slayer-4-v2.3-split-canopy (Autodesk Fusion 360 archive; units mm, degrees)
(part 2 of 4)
fillet "Fillet22" radius 6
extrude "Extrude11" new body sketch "center-lower" profile of L23 L25 C7 L29 L49 L50 L51 L52 L53 along normal blind 2 bodies "center-lower"
mirror "Mirror13" mirrorStitchTolerance 0.1
combine "Combine3"
fillet "Fillet28" radius 8
fillet "Fillet29" radius 5
fillet "Fillet30" radius 2
sketch "cam-mount-base" plane through (0, 0, 0) normal (0, 0, 1) x axis (1, 0, 0)
  line L1 (135, 0) -> (0, 0)
  line L2 (-104.9665, -10.02) -> (-84.9265, -10.02)
  line L3 (-104.9665, 10.02) -> (-104.9665, -10.02)
  line L4 (-84.9265, 10.02) -> (-104.9665, 10.02)
  line L5 (-84.9265, -10.02) -> (-84.9265, 10.02)
  line L6 (-165, 0) -> (0, 0)
  point P1 (0, 0)
  point P2 (0, 0)
  point P8 (0, 0)
  coincident P1 P2
  horizontal L1
  horizontal L2
  vertical L3
  horizontal L4
  vertical L5
  coincident P1 P8
  parallel L1 L6
  dimension "d275" distance L1 L2 = 10.02 (= "d276 / 2")
  dimension "d276" distance L2 L4 = 20.04
  dimension "d277" distance L3 L5 = 20.04 (= "d276")
extrude "Extrude15" new body sketch "cam-mount-base" profile of L2 L3 L4 L5 along normal blind 13 bodies "cam-mount-shell"
work_plane "WorkPlane1" sketch "cam-mount-base" AlongDistance 22.6
sketch "cam-mount-lens" plane through (0, 0, 22.6) normal (0, 0, 1) x axis (1, 0, 0)
  line L1 (-104.9665, 10.02) -> (-84.9265, 10.02)
  line L2 (-104.9665, -10.02) -> (-104.9665, 10.02)
  line L3 (-84.9265, -10.02) -> (-104.9665, -10.02)
  line L4 (-84.9265, 10.02) -> (-84.9265, -10.02)
  line L5 (-165, 0) -> (0, 0)
  line L6 (-94.9465, 10.02) -> (-94.9465, -10.02)
  circle C1 centre (-94.9465, 0) radius 7
  point P6 (-94.9465, 0)
  point P9 (-94.9465, -10.02)
  point P10 (-94.9465, 10.02)
  coincident P6 L5
  midpoint L3 P9
  midpoint L1 P10
  coincident P6 L6
  dimension "d281" diameter C1 = 14
loft "Loft1" sketch "cam-mount-lens"
shell "Shell1" outerThickness 1.5
extrude "Extrude16" add of existing geometry blind 2
move "Move1"
move "Move2"
sketch "Sketch25" plane through (0, 0, 2) normal (0, 0, 1) x axis (-1, 0, 0)
  line L1 (-29.0384, -18.7057) -> (-35.3306, -4.3323)
  line L2 (-7.8768, -19.0795) -> (-10.419, -18.9098)
  line L3 (10.419, -18.9098) -> (7.8768, -19.0795)
  line L4 (7.8768, 19.0795) -> (10.419, 18.9098)
  line L5 (-10.419, 18.9098) -> (-7.8768, 19.0795)
  line L6 (-35.3306, 4.3323) -> (-29.0384, 18.7057)
  line L7 (-35.4985, -3.5303) -> (-35.4985, 3.5303)
  line L8 (-28.2669, 6) -> (-24.7203, 6)
  line L9 (-29.2912, 10.6474) -> (-30.099, 8.8021)
  line L10 (-30.4985, -3) -> (-23.0892, -3)
  line L11 (-32.4985, 1) -> (-32.4985, -1)
  line L12 (-23.0892, 3) -> (-30.4985, 3)
  line L13 (15.3479, -5.782) -> (13.4133, -8.1699)
  line L14 (19.6919, -8.9044) -> (18.7852, -6.3678)
  line L15 (13.4936, -15.6979) -> (15.3167, -15.5763)
  line L16 (13.4133, 8.1699) -> (15.3479, 5.782)
  line L17 (15.3167, 15.5763) -> (13.4936, 15.6979)
  line L18 (18.7852, 6.3678) -> (19.6919, 8.9044)
  line L19 (-15.3479, 5.782) -> (-13.4133, 8.1699)
  line L20 (-19.6919, 8.9044) -> (-18.7852, 6.3678)
  line L21 (-13.4936, 15.6979) -> (-15.3167, 15.5763)
  line L22 (-13.4133, -8.1699) -> (-15.3479, -5.782)
  line L23 (-15.3167, -15.5763) -> (-13.4936, -15.6979)
  line L24 (-18.7852, -6.3678) -> (-19.6919, -8.9044)
  line L25 (-30.099, -8.8021) -> (-29.2912, -10.6474)
  line L26 (-24.7203, -6) -> (-28.2669, -6)
  line L27 (42, 0) -> (-35, 0)
  line L28 (42, -18.878) -> (42, 0)
  line L29 (-35, 0) -> (-35, -20)
  line L30 (0.0223, -24.9973) -> (-35, -20)
  line L31 (42, -18.878) -> (0.0223, -24.9973)
  line L32 (22.1379, -6.8345) -> (22.6368, -8.2301)
  line L33 (22.6368, 8.2301) -> (22.1379, 6.8345)
  arc A1 centre (-33.4985, -3.5303) radius 2 clockwise from (-35.3306, -4.3323) to (-35.4985, -3.5303)
  arc A2 centre (-24, -16.5) radius 5.5 clockwise from (-21.3581, -21.3239) to (-29.0384, -18.7057)
  arc A3 centre (-11.751, -38.8654) radius 20 clockwise from (-21.3581, -21.3239) to (-10.419, -18.9098)
  arc A4 centre (-9.0756, -37.0396) radius 18 clockwise from (-7.8768, -19.0795) to (-1.2965, -20.8073)
  arc A5 centre (0, -18.1019) radius 3 clockwise from (1.2965, -20.8073) to (-1.2965, -20.8073)
  arc A6 centre (9.0756, -37.0396) radius 18 clockwise from (1.2965, -20.8073) to (7.8768, -19.0795)
  arc A7 centre (11.751, -38.8654) radius 20 clockwise from (10.419, -18.9098) to (21.3581, -21.3239)
  arc A8 centre (24, -16.5) radius 5.5 clockwise from (25.7522, -11.2866) to (21.3581, -21.3239)
  arc A9 centre (24, 16.5) radius 5.5 clockwise from (21.3581, 21.3239) to (25.7522, 11.2866)
  arc A10 centre (11.751, 38.8654) radius 20 clockwise from (21.3581, 21.3239) to (10.419, 18.9098)
  arc A11 centre (9.0756, 37.0396) radius 18 clockwise from (7.8768, 19.0795) to (1.2965, 20.8073)
  arc A12 centre (0, 18.1019) radius 3 clockwise from (-1.2965, 20.8073) to (1.2965, 20.8073)
  arc A13 centre (-9.0756, 37.0396) radius 18 clockwise from (-1.2965, 20.8073) to (-7.8768, 19.0795)
  arc A14 centre (-11.751, 38.8654) radius 20 clockwise from (-10.419, 18.9098) to (-21.3581, 21.3239)
  arc A15 centre (-24, 16.5) radius 5.5 clockwise from (-29.0384, 18.7057) to (-21.3581, 21.3239)
  arc A16 centre (-33.4985, 3.5303) radius 2 clockwise from (-35.4985, 3.5303) to (-35.3306, 4.3323)
  arc A17 centre (-28.2669, 8) radius 2 clockwise from (-28.2669, 6) to (-30.099, 8.8021)
  arc A18 centre (-27.4591, 9.8453) radius 2 clockwise from (-29.2912, 10.6474) to (-26.5366, 11.6199)
  arc A19 centre (-30.4985, -1) radius 2 clockwise from (-30.4985, -3) to (-32.4985, -1)
  arc A20 centre (-30.4985, 1) radius 2 clockwise from (-32.4985, 1) to (-30.4985, 3)
  circle C1 centre (18.1019, 0) radius 1.05
  circle C2 centre (10, -10) radius 1.05
  circle C3 centre (24, -16.5) radius 1.55
  arc A21 centre (16.9019, -7.041) radius 2 clockwise from (15.3479, -5.782) to (18.7852, -6.3678)
  arc A22 centre (14.9837, -10.5874) radius 5 clockwise from (19.6919, -8.9044) to (15.3167, -15.5763)
  arc A23 centre (13.3604, -13.7024) radius 2 clockwise from (13.4936, -15.6979) to (12.0163, -12.2214)
  arc A24 centre (10, -10) radius 3 clockwise from (12.9804, -9.6573) to (12.0163, -12.2214)
  arc A25 centre (14.9673, -9.4289) radius 2 clockwise from (12.9804, -9.6573) to (13.4133, -8.1699)
  arc A26 centre (14.9673, 9.4289) radius 2 clockwise from (13.4133, 8.1699) to (12.9804, 9.6573)
  arc A27 centre (10, 10) radius 3 clockwise from (12.0163, 12.2214) to (12.9804, 9.6573)
  arc A28 centre (13.3604, 13.7024) radius 2 clockwise from (12.0163, 12.2214) to (13.4936, 15.6979)
  arc A29 centre (14.9837, 10.5874) radius 5 clockwise from (15.3167, 15.5763) to (19.6919, 8.9044)
  arc A30 centre (16.9019, 7.041) radius 2 clockwise from (18.7852, 6.3678) to (15.3479, 5.782)
  circle C4 centre (24, 16.5) radius 1.55
  circle C5 centre (10, 10) radius 1.05
  circle C6 centre (-10, 10) radius 1.05
  circle C7 centre (-24, 16.5) radius 1.55
  arc A31 centre (-16.9019, 7.041) radius 2 clockwise from (-15.3479, 5.782) to (-18.7852, 6.3678)
  arc A32 centre (-14.9837, 10.5874) radius 5 clockwise from (-19.6919, 8.9044) to (-15.3167, 15.5763)
  arc A33 centre (-13.3604, 13.7024) radius 2 clockwise from (-13.4936, 15.6979) to (-12.0163, 12.2214)
  arc A34 centre (-10, 10) radius 3 clockwise from (-12.9804, 9.6573) to (-12.0163, 12.2214)
  arc A35 centre (-14.9673, 9.4289) radius 2 clockwise from (-12.9804, 9.6573) to (-13.4133, 8.1699)
  arc A36 centre (-14.9673, -9.4289) radius 2 clockwise from (-13.4133, -8.1699) to (-12.9804, -9.6573)
  arc A37 centre (-10, -10) radius 3 clockwise from (-12.0163, -12.2214) to (-12.9804, -9.6573)
  arc A38 centre (-13.3604, -13.7024) radius 2 clockwise from (-12.0163, -12.2214) to (-13.4936, -15.6979)
  arc A39 centre (-14.9837, -10.5874) radius 5 clockwise from (-15.3167, -15.5763) to (-19.6919, -8.9044)
  arc A40 centre (-16.9019, -7.041) radius 2 clockwise from (-18.7852, -6.3678) to (-15.3479, -5.782)
  circle C8 centre (-24, -16.5) radius 1.55
  circle C9 centre (-10, -10) radius 1.05
  circle C10 centre (-18.1019, 0) radius 1.05
  circle C11 centre (0, -18.1019) radius 1.05
  circle C12 centre (0, 18.1019) radius 1.05
  arc A41 centre (0, 3.3668) radius 9 clockwise from (-7.5, 8.3417) to (7.5, 8.3417)
  arc A42 centre (10, 10) radius 3 clockwise from (8.3417, 7.5) to (7.5, 8.3417)
  arc A43 centre (3.3668, 0) radius 9 clockwise from (8.3417, 7.5) to (8.3417, -7.5)
  arc A44 centre (10, -10) radius 3 clockwise from (7.5, -8.3417) to (8.3417, -7.5)
  arc A45 centre (0, -3.3668) radius 9 clockwise from (7.5, -8.3417) to (-7.5, -8.3417)
  arc A46 centre (-10, -10) radius 3 clockwise from (-8.3417, -7.5) to (-7.5, -8.3417)
  arc A47 centre (-3.3668, 0) radius 9 clockwise from (-8.3417, -7.5) to (-8.3417, 7.5)
  arc A48 centre (-10, 10) radius 3 clockwise from (-7.5, 8.3417) to (-8.3417, 7.5)
  arc A49 centre (-27.4591, -9.8453) radius 2 clockwise from (-26.5366, -11.6199) to (-29.2912, -10.6474)
  arc A50 centre (-28.2669, -8) radius 2 clockwise from (-30.099, -8.8021) to (-28.2669, -6)
  arc A51 centre (27.345, -6.5471) radius 5 clockwise from (25.7522, -11.2866) to (22.6368, -8.2301)
  arc A52 centre (39.0876, -0.7757) radius 18 clockwise from (22.1379, -6.8345) to (21.0999, -0.1108)
  arc A53 centre (18.1019, 0) radius 3 clockwise from (21.0999, 0.1108) to (21.0999, -0.1108)
  arc A54 centre (39.0876, 0.7757) radius 18 clockwise from (21.0999, 0.1108) to (22.1379, 6.8345)
  arc A55 centre (27.345, 6.5471) radius 5 clockwise from (22.6368, 8.2301) to (25.7522, 11.2866)
  arc A56 centre (-24, 16.5) radius 5.5 clockwise from (-25.7522, 11.2866) to (-26.5366, 11.6199)
  arc A57 centre (-27.345, 6.5471) radius 5 clockwise from (-25.7522, 11.2866) to (-22.9705, 8.9686)
  arc A58 centre (-24.7203, 8) radius 2 clockwise from (-22.9705, 8.9686) to (-24.7203, 6)
  arc A59 centre (-24.7203, -8) radius 2 clockwise from (-24.7203, -6) to (-22.9705, -8.9686)
  arc A60 centre (-27.345, -6.5471) radius 5 clockwise from (-22.9705, -8.9686) to (-25.7522, -11.2866)
  arc A61 centre (-24, -16.5) radius 5.5 clockwise from (-26.5366, -11.6199) to (-25.7522, -11.2866)
  arc A62 centre (-39.0876, 0.7757) radius 18 clockwise from (-21.0894, 1.028) to (-21.0999, 0.1108)
  arc A63 centre (-18.1019, 0) radius 3 clockwise from (-21.0999, -0.1108) to (-21.0999, 0.1108)
  arc A64 centre (-39.0876, -0.7757) radius 18 clockwise from (-21.0999, -0.1108) to (-21.0894, -1.028)
  arc A65 centre (-23.0892, -1) radius 2 clockwise from (-21.0894, -1.028) to (-23.0892, -3)
  arc A66 centre (-23.0892, 1) radius 2 clockwise from (-23.0892, 3) to (-21.0894, 1.028)
  horizontal L27
  vertical L28
  vertical L29
extrude "Extrude26" new body sketch "Sketch25" profile of A1 L1 A2 A3 L2 A4 A5 A6 L3 A7 A8 L7 L10 A19 L11 C1 C2 C3 L13 A21 L14 A22 L15 A23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 along normal blind 43
sketch "Sketch33" plane through (0, 0, 0) normal (0, -1, 0) x axis (1, 0, 0)
  line L1 (35, 2) -> (-42, 2)
  line L2 (35, 45) -> (35, 2)
  line L3 (-42, 45) -> (35, 45)
  line L4 (-42, 2) -> (-42, 45)
  line L5 (35, 27.2231) -> (-42, 45)
  point P5 (-42, 45)
  point P6 (-42, 45)
  point P7 (35, 27.2231)
  coincident P5 P6
  coincident L2 P7
  dimension "d678" angle L3 L5 = 13
extrude "Extrude45" cut sketch "Sketch33" profile of L2 L3 L5 against normal blind 29
chamfer "Chamfer4" distance 12 Rotate Angle 35
chamfer "Chamfer5" distance 15 Rotate Angle 30
work_plane "WorkPlane14" RotateAngle 77 (= "90 deg - 13 deg")
sketch "Sketch50" plane through (-49.738, 0, 11.4829) normal (-0.9744, 0, 0.225) x axis (0, -1, 0)
  line L1 (0, 34.3987) -> (-9.322, 34.3987)
  line L2 (-38.1198, 34.3987) -> (0, 34.3987)
  line L3 (-38.1198, 9.6434) -> (-38.1198, 34.3987)
  line L4 (-38.1198, 9.6434) -> (0, 34.3987)
  point P3 (0, 34.3987)
  point P4 (0, 34.3987)
  point P7 (0, 34.3987)
  coincident P3 P4
  parallel L1 L2
  perpendicular L1 L3
  coincident P3 P7
  dimension "d680" angle L2 L4 = 33
extrude "Extrude72" cut sketch "Sketch50" against normal blind 97
sketch "Sketch26" plane through (0, 0, 0) normal (0, -1, 0) x axis (1, 0, 0)
  line L1 (-42, 2) -> (-42, 45)
  line L2 (35, 2) -> (-42, 2)
  line L3 (35, 27.2231) -> (35, 2)
  line L4 (-19, 2) -> (-19, 35)
  line L5 (-42, 45) -> (35, 27.2231)
  line L6 (35, 27.2231) -> (45.0403, 62.0037)
  curve K1 (-19, 35) -> (45.0403, 62.0037)
  curve K2 (40, 64) -> (50.0806, 60.0075)
  curve K3 (-24, 35) -> (-14, 35)
  line L7 (-42, 35) -> (-19, 35)
  point P6 (-19, 2)
  point P5 (35, 27.2231)
  point P7 (35, 27.2231)
  point P10 (45.0403, 62.0037)
  point P15 (-19, 35)
  point P16 (-42, 35)
  coincident L2 P6
  perpendicular L2 L4
  coincident P5 P7
  midpoint P10 K2
  midpoint K3 P15
  coincident L1 P16
  perpendicular L1 L7
  dimension "d688" distance P6 P15 = 33
extrude "Extrude73" cut sketch "Sketch26" profile of L1 L5 K1 L7 against normal blind 69
extrude "Extrude27" add sketch "Sketch26" profile of L2 L3 L4 L5 L6 K1 against normal blind 2.4
move "Move3"
split "Split1" bodies "cam-mount-shell (1)"
extrude "Extrude36" cut of existing geometry blind -17
sketch "Sketch30" plane through (0, 0, 0) normal (0, -1, 0) x axis (1, 0, 0)
  line L1 (-42, 2) -> (-42, 35)
  line L2 (35, 2) -> (-42, 2)
  line L3 (35, 27.2231) -> (35, 2)
  line L4 (-4.0783, 67.2737) -> (-42, 2)
  line L5 (45.0403, 62.0037) -> (35, 27.2231)
  line L6 (-42, 35) -> (-19, 35)
  curve K1 (-9.0663, 37.3967) -> (45.0403, 62.0037)
  curve K2 (-19, 35) -> (-9.0663, 37.3967)
  point P3 (-42, 2)
  point P6 (-42, 2)
  point P12 (-27.1569, 27.5491)
  coincident P3 P6
  coincident L4 P12
extrude "Extrude37" cut sketch "Sketch30" profile of L1 L4 against normal blind 24
sketch "Sketch31" plane through (-35.0636, 0, 35.0636) normal (-0.7071, 0, 0.7071) x axis (0, -1, 0)
  line L1 (0, -1.4655) -> (0, -3.038)
  line L2 (0, -17.038) -> (0, -18.6105)
  line L3 (0, -19.238) -> (0, -0.838)
  circle C1 centre (0, -10.038) radius 9.2
  circle C2 centre (0, -10.038) radius 7.2
  point P7 (0, -0.838)
  point P8 (0, -19.238)
  coincident C1 P7
  coincident C1 P8
  parallel L2 L3
  concentric C1 C2
  dimension "d424" diameter C2 = 14.4
loft "Loft6" sketch "Sketch31"
shell "Shell5" innerThickness 1.4
extrude "Extrude39" cut of existing geometry blind -3
component_insert "Component Insert1"
extrude "Extrude40" cut sketch "Sketch31" profile of L3 C2 against normal blind 6
extrude "Extrude44" add of existing geometry blind -6
chamfer "Chamfer6" distance 2 Rotate Angle 45
component_insert "Component Insert2"
position "Position2"
component_insert "Component Insert3"
position "Position3"
component_insert "Component Insert4"
position "Position4"
component_insert "Component Insert5"
position "Position5"
sketch "Sketch34" plane through (0, 0, 2) normal (0, 0, -1) x axis (1, 0, 0)
  line L1 (-42, -9.322) -> (-42, 0)
  line L2 (25.6648, -21.332) -> (-0.0223, -24.9973)
  line L3 (35, -8) -> (25.6648, -21.332)
  line L4 (35, 0) -> (35, -8)
  line L5 (-40.5206, 0) -> (-40.5206, -1.4)
  line L6 (33.6, -7.5586) -> (33.6, 0)
  line L7 (24.8662, -20.0318) -> (33.6, -7.5586)
  line L8 (-0.0202, -23.5828) -> (24.8662, -20.0318)
  curve K1 (-40.5206, -1.4) -> (-40.5362, -8.694)
  line L9 (2.5, 0) -> (20, 0)
  line L10 (-32.4922, -15.0454) -> (-33.3597, -16.1441)
  line L11 (-42, 0) -> (-40.5206, 0)
  line L12 (33.6, 0) -> (35, 0)
  line L13 (-27.1569, -21.0418) -> (-42, -9.322)
  line L14 (-0.0223, -24.9973) -> (-27.1569, -21.0418)
  line L15 (-26.5837, -19.7105) -> (-0.0202, -23.5828)
  line L16 (-40.5362, -8.694) -> (-26.5837, -19.7105)
  point P19 (-33.3597, -16.1441)
  point P20 (-32.4922, -15.0454)
  coincident P19 L13
  perpendicular L10 L13
  coincident P20 L16
sketch "Sketch35" plane through (0, 0, -7) normal (0, 0, -1) x axis (1, 0, 0)
  line L1 (-40.0019, -3.8052) -> (-40.0019, 3.8052)
  line L2 (-32.3778, -13.0107) -> (-38.3863, -7.4856)
  line L3 (-10.5918, -15.9571) -> (-11.8125, -16.192)
  line L4 (9.4583, -15.8491) -> (-9.4583, -15.8491)
  line L5 (11.8125, -16.192) -> (10.5918, -15.9571)
  line L6 (25.5, 3.8608) -> (25.5, -3.8608)
  line L7 (10.5918, 15.9571) -> (11.8125, 16.192)
  line L8 (-9.4583, 15.8491) -> (9.4583, 15.8491)
  line L9 (-11.8125, 16.192) -> (-10.5918, 15.9571)
  line L10 (-38.3863, 7.4856) -> (-32.3778, 13.0107)
  line L11 (-28.2365, -6) -> (-30.4401, -6)
  line L12 (-31.7938, -9.4722) -> (-30.229, -10.9111)
  line L13 (-37.0019, 1) -> (-37.0019, -1)
  line L14 (-27.5, 3) -> (-35.0019, 3)
  line L15 (-25.5, -1) -> (-25.5, 1)
  line L16 (-35.0019, -3) -> (-27.5, -3)
  line L17 (-30.4401, 6) -> (-28.2365, 6)
  line L18 (-30.229, 10.9111) -> (-31.7938, 9.4722)
  line L19 (22.5, -4.5203) -> (22.5, 4.5203)
  curve K1 (22.5, -4.5203) -> (19.2416, -6.0748)
  curve K2 (15, 0) -> (19.2416, -6.0748)
  curve K3 (15, 0) -> (19.2416, 6.0748)
  curve K4 (22.5, 4.5203) -> (19.2416, 6.0748)
  line L20 (-4.9888, -4) -> (-8.485, -4)
  line L21 (-1.2286, -8.8428) -> (-3.2198, -5.0671)
  line L22 (-9.9931, -11.7757) -> (-2.9977, -11.7757)
  curve K5 (-11.9135, -8.8933) -> (-10.0564, -11.7767)
  curve K6 (-19.8418, -20.8254) -> (-19.3632, -20.3456)
  line L23 (4.916, -11.7757) -> (9.9931, -11.7757)
  line L24 (1.1558, -6.9329) -> (3.1469, -10.7087)
  line L25 (8.485, -4) -> (2.9249, -4)
  curve K7 (19.8418, -20.8254) -> (19.3632, -20.3456)
  curve K8 (11.9135, -8.8933) -> (10.0564, -11.7767)
  line L26 (9.9931, 11.7757) -> (4.916, 11.7757)
  curve K9 (11.9135, 8.8933) -> (10.0564, 11.7767)
  curve K10 (19.8418, 20.8254) -> (19.3632, 20.3456)
  line L27 (2.9249, 4) -> (8.485, 4)
  line L28 (3.1469, 10.7087) -> (1.1558, 6.9329)
  curve K11 (-15, 0) -> (-19.2416, -6.0748)
  curve K12 (-22.5, -4.5203) -> (-19.2416, -6.0748)
  line L29 (-22.5, 4.5203) -> (-22.5, -4.5203)
  curve K13 (-22.5, 4.5203) -> (-19.2416, 6.0748)
  curve K14 (-15, 0) -> (-19.2416, 6.0748)
  curve K15 (-19.8418, 20.8254) -> (-19.3632, 20.3456)
  curve K16 (-11.9135, 8.8933) -> (-10.0564, 11.7767)
  line L30 (-3.2198, 5.0671) -> (-1.2286, 8.8428)
  line L31 (-89, 0) -> (0, 0)
  line L32 (-41.4019, -6.6146) -> (-33.1399, -14.2119)
  line L33 (-33.1399, -14.2119) -> (-32.1923, -13.1813)
  line L34 (-41.4019, -6.6146) -> (-41.4019, 0)
  line L35 (-40.0019, 0) -> (-41.4019, 0)
  curve K17 (-11.8125, -16.192) -> (-19.3632, -20.3456)
  curve K18 (11.8125, -16.192) -> (19.3632, -20.3456)
  curve K19 (11.8125, 16.192) -> (19.3632, 20.3456)
  curve K20 (-11.8125, 16.192) -> (-19.3632, 20.3456)
  curve K21 (10.0564, 11.7767) -> (9.9931, 11.7757)
  curve K22 (11.9135, 8.8933) -> (10.3646, 5.3164)
  curve K23 (10.3646, 5.3164) -> (8.485, 4)
  curve K24 (-11.9135, 8.8933) -> (-10.3646, 5.3164)
  curve K25 (-10.0564, 11.7767) -> (-9.9931, 11.7757)
  line L36 (-2.9977, 11.7757) -> (-9.9931, 11.7757)
  line L37 (-8.485, 4) -> (-4.9888, 4)
  curve K26 (-8.485, 4) -> (-10.3646, 5.3164)
  curve K27 (-11.9135, -8.8933) -> (-10.3646, -5.3164)
  curve K28 (-8.485, -4) -> (-10.3646, -5.3164)
  curve K29 (-10.0564, -11.7767) -> (-9.9931, -11.7757)
  curve K30 (10.3646, -5.3164) -> (8.485, -4)
  curve K31 (11.9135, -8.8933) -> (10.3646, -5.3164)
  curve K32 (10.0564, -11.7767) -> (9.9931, -11.7757)
  arc A1 centre (-35.0019, 3.8052) radius 5 clockwise from (-40.0019, 3.8052) to (-38.3863, 7.4856)
  arc A2 centre (-35.0019, -3.8052) radius 5 clockwise from (-38.3863, -7.4856) to (-40.0019, -3.8052)
  arc A3 centre (-37.7928, -18.8995) radius 8 clockwise from (-32.3778, -13.0107) to (-29.9112, -17.5284)
  arc A4 centre (-24, -16.5) radius 6 clockwise from (-19.8418, -20.8254) to (-29.9112, -17.5284)
  arc A5 centre (-9.4583, -21.8491) radius 6 clockwise from (-10.5918, -15.9571) to (-9.4583, -15.8491)
  arc A6 centre (9.4583, -21.8491) radius 6 clockwise from (9.4583, -15.8491) to (10.5918, -15.9571)
  arc A7 centre (24, -16.5) radius 6 clockwise from (28.65, -12.7082) to (19.8418, -20.8254)
  arc A8 centre (24, 16.5) radius 6 clockwise from (19.8418, 20.8254) to (28.65, 12.7082)
  arc A9 centre (9.4583, 21.8491) radius 6 clockwise from (10.5918, 15.9571) to (9.4583, 15.8491)
  arc A10 centre (-9.4583, 21.8491) radius 6 clockwise from (-9.4583, 15.8491) to (-10.5918, 15.9571)
  arc A11 centre (-24, 16.5) radius 6 clockwise from (-29.9112, 17.5284) to (-19.8418, 20.8254)
  arc A12 centre (-37.7928, 18.8995) radius 8 clockwise from (-29.9112, 17.5284) to (-32.3778, 13.0107)
  arc A13 centre (-30.4401, -8) radius 2 clockwise from (-31.7938, -9.4722) to (-30.4401, -6)
  arc A14 centre (-35.0019, 1) radius 2 clockwise from (-37.0019, 1) to (-35.0019, 3)
  arc A15 centre (-27.5, 1) radius 2 clockwise from (-27.5, 3) to (-25.5, 1)
  arc A16 centre (-27.5, -1) radius 2 clockwise from (-25.5, -1) to (-27.5, -3)
  arc A17 centre (-35.0019, -1) radius 2 clockwise from (-35.0019, -3) to (-37.0019, -1)
  arc A18 centre (-30.4401, 8) radius 2 clockwise from (-30.4401, 6) to (-31.7938, 9.4722)
  arc A19 centre (-4.9888, -6) radius 2 clockwise from (-4.9888, -4) to (-3.2198, -5.0671)
  arc A20 centre (-2.9977, -9.7757) radius 2 clockwise from (-1.2286, -8.8428) to (-2.9977, -11.7757)
  circle C1 centre (-24, -16.5) radius 1.55
  circle C2 centre (24, -16.5) radius 1.55
  arc A21 centre (4.916, -9.7757) radius 2 clockwise from (4.916, -11.7757) to (3.1469, -10.7087)
  arc A22 centre (2.9249, -6) radius 2 clockwise from (1.1558, -6.9329) to (2.9249, -4)
  arc A23 centre (2.9249, 6) radius 2 clockwise from (2.9249, 4) to (1.1558, 6.9329)
  arc A24 centre (4.916, 9.7757) radius 2 clockwise from (3.1469, 10.7087) to (4.916, 11.7757)
  circle C3 centre (24, 16.5) radius 1.55
  circle C4 centre (-24, 16.5) radius 1.55
  arc A25 centre (-2.9977, 9.7757) radius 2 clockwise from (-2.9977, 11.7757) to (-1.2286, 8.8428)
  arc A26 centre (-4.9888, 6) radius 2 clockwise from (-3.2198, 5.0671) to (-4.9888, 4)
  arc A27 centre (-39.5, -3.8608) radius 14 clockwise from (-26.3592, -8.6899) to (-27.1045, -10.3686)
  arc A28 centre (-28.8753, -9.4389) radius 2 clockwise from (-27.1045, -10.3686) to (-30.229, -10.9111)
  arc A29 centre (-28.2365, -8) radius 2 clockwise from (-28.2365, -6) to (-26.3592, -8.6899)
  arc A30 centre (39.5, -3.8608) radius 14 clockwise from (28.65, -12.7082) to (25.5, -3.8608)
  arc A31 centre (39.5, 3.8608) radius 14 clockwise from (25.5, 3.8608) to (28.65, 12.7082)
  arc A32 centre (-28.8753, 9.4389) radius 2 clockwise from (-30.229, 10.9111) to (-27.1045, 10.3686)
  arc A33 centre (-39.5, 3.8608) radius 14 clockwise from (-27.1045, 10.3686) to (-26.3592, 8.6899)
  arc A34 centre (-28.2365, 8) radius 2 clockwise from (-26.3592, 8.6899) to (-28.2365, 6)
  point P1 (0, 0)
  point P113 (0, 0)
  point P115 (-41.4019, 0)
  point P119 (-41.4019, 0)
  point P120 (-40.0019, 0)
  point P118 (-32.1923, -13.1813)
  coincident P1 P113
  horizontal L31
  coincident L31 P115
  symmetric L31 P115 P119
  midpoint L1 P120
  parallel L2 L32
  coincident L2 P118
  perpendicular L2 L33
  dimension "d791" distance L1 L34 = 1.4
  dimension "d792" distance L2 L32 = 1.4
loft "Loft7" sketch "Sketch34" + "Sketch35"
sketch "Sketch36" plane through (0, 0, 2) normal (0, 0, 1) x axis (-1, 0, 0)
  line L1 (-29.0384, -18.7057) -> (-35.3306, -4.3323)
  line L2 (-7.8768, -19.0795) -> (-10.419, -18.9098)
  line L3 (10.419, -18.9098) -> (7.8768, -19.0795)
  line L4 (7.8768, 19.0795) -> (10.419, 18.9098)
  line L5 (-10.419, 18.9098) -> (-7.8768, 19.0795)
  line L6 (-35.3306, 4.3323) -> (-29.0384, 18.7057)
  line L7 (-35.4985, -3.5303) -> (-35.4985, 3.5303)
  line L8 (-28.2669, 6) -> (-24.7203, 6)
  line L9 (-29.2912, 10.6474) -> (-30.099, 8.8021)
  line L10 (-30.4985, -3) -> (-23.0892, -3)
  line L11 (-32.4985, 1) -> (-32.4985, -1)
  line L12 (-23.0892, 3) -> (-30.4985, 3)
  line L13 (15.3479, -5.782) -> (13.4133, -8.1699)
  line L14 (19.6919, -8.9044) -> (18.7852, -6.3678)
  line L15 (13.4936, -15.6979) -> (15.3167, -15.5763)
  line L16 (13.4133, 8.1699) -> (15.3479, 5.782)
  line L17 (15.3167, 15.5763) -> (13.4936, 15.6979)
  line L18 (18.7852, 6.3678) -> (19.6919, 8.9044)
  line L19 (-15.3479, 5.782) -> (-13.4133, 8.1699)
  line L20 (-19.6919, 8.9044) -> (-18.7852, 6.3678)
  line L21 (-13.4936, 15.6979) -> (-15.3167, 15.5763)
  line L22 (-13.4133, -8.1699) -> (-15.3479, -5.782)
  line L23 (-15.3167, -15.5763) -> (-13.4936, -15.6979)
  line L24 (-18.7852, -6.3678) -> (-19.6919, -8.9044)
  line L25 (-30.099, -8.8021) -> (-29.2912, -10.6474)
  line L26 (-24.7203, -6) -> (-28.2669, -6)
  line L27 (-2.5, 0) -> (-20, 0)
  line L28 (22.1379, -6.8345) -> (22.6368, -8.2301)
  line L29 (22.6368, 8.2301) -> (22.1379, 6.8345)
  arc A1 centre (-33.4985, -3.5303) radius 2 clockwise from (-35.3306, -4.3323) to (-35.4985, -3.5303)
  arc A2 centre (-24, -16.5) radius 5.5 clockwise from (-21.3581, -21.3239) to (-29.0384, -18.7057)
  arc A3 centre (-11.751, -38.8654) radius 20 clockwise from (-21.3581, -21.3239) to (-10.419, -18.9098)
  arc A4 centre (-9.0756, -37.0396) radius 18 clockwise from (-7.8768, -19.0795) to (-1.2965, -20.8073)
  arc A5 centre (0, -18.1019) radius 3 clockwise from (1.2965, -20.8073) to (-1.2965, -20.8073)
  arc A6 centre (9.0756, -37.0396) radius 18 clockwise from (1.2965, -20.8073) to (7.8768, -19.0795)
  arc A7 centre (11.751, -38.8654) radius 20 clockwise from (10.419, -18.9098) to (21.3581, -21.3239)
  arc A8 centre (24, -16.5) radius 5.5 clockwise from (25.7522, -11.2866) to (21.3581, -21.3239)
  arc A9 centre (24, 16.5) radius 5.5 clockwise from (21.3581, 21.3239) to (25.7522, 11.2866)
  arc A10 centre (11.751, 38.8654) radius 20 clockwise from (21.3581, 21.3239) to (10.419, 18.9098)
  arc A11 centre (9.0756, 37.0396) radius 18 clockwise from (7.8768, 19.0795) to (1.2965, 20.8073)
  arc A12 centre (0, 18.1019) radius 3 clockwise from (-1.2965, 20.8073) to (1.2965, 20.8073)
  arc A13 centre (-9.0756, 37.0396) radius 18 clockwise from (-1.2965, 20.8073) to (-7.8768, 19.0795)
  arc A14 centre (-11.751, 38.8654) radius 20 clockwise from (-10.419, 18.9098) to (-21.3581, 21.3239)
  arc A15 centre (-24, 16.5) radius 5.5 clockwise from (-29.0384, 18.7057) to (-21.3581, 21.3239)
  arc A16 centre (-33.4985, 3.5303) radius 2 clockwise from (-35.4985, 3.5303) to (-35.3306, 4.3323)
  arc A17 centre (-28.2669, 8) radius 2 clockwise from (-28.2669, 6) to (-30.099, 8.8021)
  arc A18 centre (-27.4591, 9.8453) radius 2 clockwise from (-29.2912, 10.6474) to (-26.5366, 11.6199)
  arc A19 centre (-30.4985, -1) radius 2 clockwise from (-30.4985, -3) to (-32.4985, -1)
  arc A20 centre (-30.4985, 1) radius 2 clockwise from (-32.4985, 1) to (-30.4985, 3)
  circle C1 centre (18.1019, 0) radius 1.05
  circle C2 centre (10, -10) radius 1.05
  circle C3 centre (24, -16.5) radius 1.55
  arc A21 centre (16.9019, -7.041) radius 2 clockwise from (15.3479, -5.782) to (18.7852, -6.3678)
  arc A22 centre (14.9837, -10.5874) radius 5 clockwise from (19.6919, -8.9044) to (15.3167, -15.5763)
  arc A23 centre (13.3604, -13.7024) radius 2 clockwise from (13.4936, -15.6979) to (12.0163, -12.2214)
  arc A24 centre (10, -10) radius 3 clockwise from (12.9804, -9.6573) to (12.0163, -12.2214)
  arc A25 centre (14.9673, -9.4289) radius 2 clockwise from (12.9804, -9.6573) to (13.4133, -8.1699)
  arc A26 centre (14.9673, 9.4289) radius 2 clockwise from (13.4133, 8.1699) to (12.9804, 9.6573)
  arc A27 centre (10, 10) radius 3 clockwise from (12.0163, 12.2214) to (12.9804, 9.6573)
  arc A28 centre (13.3604, 13.7024) radius 2 clockwise from (12.0163, 12.2214) to (13.4936, 15.6979)
  arc A29 centre (14.9837, 10.5874) radius 5 clockwise from (15.3167, 15.5763) to (19.6919, 8.9044)
  arc A30 centre (16.9019, 7.041) radius 2 clockwise from (18.7852, 6.3678) to (15.3479, 5.782)
  circle C4 centre (24, 16.5) radius 1.55
  circle C5 centre (10, 10) radius 1.05
  circle C6 centre (-10, 10) radius 1.05
  circle C7 centre (-24, 16.5) radius 1.55
  arc A31 centre (-16.9019, 7.041) radius 2 clockwise from (-15.3479, 5.782) to (-18.7852, 6.3678)
  arc A32 centre (-14.9837, 10.5874) radius 5 clockwise from (-19.6919, 8.9044) to (-15.3167, 15.5763)
  arc A33 centre (-13.3604, 13.7024) radius 2 clockwise from (-13.4936, 15.6979) to (-12.0163, 12.2214)
  arc A34 centre (-10, 10) radius 3 clockwise from (-12.9804, 9.6573) to (-12.0163, 12.2214)
  arc A35 centre (-14.9673, 9.4289) radius 2 clockwise from (-12.9804, 9.6573) to (-13.4133, 8.1699)
  arc A36 centre (-14.9673, -9.4289) radius 2 clockwise from (-13.4133, -8.1699) to (-12.9804, -9.6573)
  arc A37 centre (-10, -10) radius 3 clockwise from (-12.0163, -12.2214) to (-12.9804, -9.6573)
  arc A38 centre (-13.3604, -13.7024) radius 2 clockwise from (-12.0163, -12.2214) to (-13.4936, -15.6979)
  arc A39 centre (-14.9837, -10.5874) radius 5 clockwise from (-15.3167, -15.5763) to (-19.6919, -8.9044)
  arc A40 centre (-16.9019, -7.041) radius 2 clockwise from (-18.7852, -6.3678) to (-15.3479, -5.782)
  circle C8 centre (-24, -16.5) radius 1.55
  circle C9 centre (-10, -10) radius 1.05
  circle C10 centre (-18.1019, 0) radius 1.05
  circle C11 centre (0, -18.1019) radius 1.05
  circle C12 centre (0, 18.1019) radius 1.05
  arc A41 centre (0, 3.3668) radius 9 clockwise from (-7.5, 8.3417) to (7.5, 8.3417)
  arc A42 centre (10, 10) radius 3 clockwise from (8.3417, 7.5) to (7.5, 8.3417)
  arc A43 centre (3.3668, 0) radius 9 clockwise from (8.3417, 7.5) to (8.3417, -7.5)
  arc A44 centre (10, -10) radius 3 clockwise from (7.5, -8.3417) to (8.3417, -7.5)
  arc A45 centre (0, -3.3668) radius 9 clockwise from (7.5, -8.3417) to (-7.5, -8.3417)
  arc A46 centre (-10, -10) radius 3 clockwise from (-8.3417, -7.5) to (-7.5, -8.3417)
  arc A47 centre (-3.3668, 0) radius 9 clockwise from (-8.3417, -7.5) to (-8.3417, 7.5)
  arc A48 centre (-10, 10) radius 3 clockwise from (-7.5, 8.3417) to (-8.3417, 7.5)
  arc A49 centre (-27.4591, -9.8453) radius 2 clockwise from (-26.5366, -11.6199) to (-29.2912, -10.6474)
  arc A50 centre (-28.2669, -8) radius 2 clockwise from (-30.099, -8.8021) to (-28.2669, -6)
  circle C13 centre (24, -16.5) radius 3.25
  circle C14 centre (-24, -16.5) radius 3.25
  circle C15 centre (24, -16.5) radius 4.85
  circle C16 centre (-24, -16.5) radius 4.85
  arc A51 centre (27.345, -6.5471) radius 5 clockwise from (25.7522, -11.2866) to (22.6368, -8.2301)
  arc A52 centre (39.0876, -0.7757) radius 18 clockwise from (22.1379, -6.8345) to (21.0999, -0.1108)
  arc A53 centre (18.1019, 0) radius 3 clockwise from (21.0999, 0.1108) to (21.0999, -0.1108)
  arc A54 centre (39.0876, 0.7757) radius 18 clockwise from (21.0999, 0.1108) to (22.1379, 6.8345)
  arc A55 centre (27.345, 6.5471) radius 5 clockwise from (22.6368, 8.2301) to (25.7522, 11.2866)
  arc A56 centre (-24, 16.5) radius 5.5 clockwise from (-25.7522, 11.2866) to (-26.5366, 11.6199)
  arc A57 centre (-27.345, 6.5471) radius 5 clockwise from (-25.7522, 11.2866) to (-22.9705, 8.9686)
  arc A58 centre (-24.7203, 8) radius 2 clockwise from (-22.9705, 8.9686) to (-24.7203, 6)
  arc A59 centre (-24.7203, -8) radius 2 clockwise from (-24.7203, -6) to (-22.9705, -8.9686)
  arc A60 centre (-27.345, -6.5471) radius 5 clockwise from (-22.9705, -8.9686) to (-25.7522, -11.2866)
  arc A61 centre (-24, -16.5) radius 5.5 clockwise from (-26.5366, -11.6199) to (-25.7522, -11.2866)
  arc A62 centre (-39.0876, 0.7757) radius 18 clockwise from (-21.0894, 1.028) to (-21.0999, 0.1108)
  arc A63 centre (-18.1019, 0) radius 3 clockwise from (-21.0999, -0.1108) to (-21.0999, 0.1108)
  arc A64 centre (-39.0876, -0.7757) radius 18 clockwise from (-21.0999, -0.1108) to (-21.0894, -1.028)
  arc A65 centre (-23.0892, -1) radius 2 clockwise from (-21.0894, -1.028) to (-23.0892, -3)
  arc A66 centre (-23.0892, 1) radius 2 clockwise from (-23.0892, 3) to (-21.0894, 1.028)
  concentric A8 C13
  concentric A2 C14
  concentric A8 C15
  concentric A2 C16
  dimension "d464" diameter C13 = 6.5
  dimension "d465" diameter C14 = 6.5 (= "d464")
  dimension "d466" distance C13 C15 = 1.6
  dimension "d467" distance C14 C16 = 1.6 (= "d466")
chamfer "Chamfer13" distance 5
extrude "Extrude46" new body sketch "Sketch36" profile of L1 A2 A3 A7 A8 C3 C8 A49 C13 C14 C15 C16 along normal blind 40
extrude "Extrude76" cut of existing geometry blind -10
combine "Combine6"
combine "Combine7"
remove_body "RemoveBody30"
remove_body "RemoveBody41"
combine "Combine8"
combine "Combine26"
extrude "Extrude48" cut sketch "Sketch36" profile of C3 C8 C13 C14 along normal blind 15
work_plane "WorkPlane5" sketch "Sketch36" AlongDistance 17
sketch "Sketch37" plane through (0, 0, 19) normal (0, 0, 1) x axis (1, 0, 0)
  line L1 (-32.4922, 15.0454) -> (-28.5609, 18.1494)
  line L2 (-33.3597, 16.1441) -> (-32.4922, 15.0454)
  line L3 (-27.1569, 21.0418) -> (-33.3597, 16.1441)
  line L4 (-0.0223, 24.9973) -> (-27.1569, 21.0418)
  line L5 (20.715, 22.0383) -> (-0.0223, 24.9973)
  line L6 (-0.0202, 23.5828) -> (19.9163, 20.7381)
  line L7 (-21.2417, 20.4893) -> (-0.0202, 23.5828)
  line L8 (35, 8) -> (28.5327, 17.2363)
  line L9 (35, 0) -> (35, 8)
  line L10 (33.6, 0) -> (35, 0)
  line L11 (33.6, 7.5586) -> (33.6, 0)
  line L12 (27.734, 15.936) -> (33.6, 7.5586)
  line L13 (19.9163, 20.7381) -> (22.3032, 19.2719)
  line L14 (24.5045, 19.7106) -> (20.715, 22.0383)
  line L15 (28.5327, 17.2363) -> (26.6357, 18.4015)
  line L16 (27.2396, 16.2398) -> (27.734, 15.936)
  circle C1 centre (-24, 16.5) radius 4.85
  circle C2 centre (-24, 16.5) radius 3.25
  circle C3 centre (24, 16.5) radius 4.85
  circle C4 centre (24, 16.5) radius 3.25
  arc A1 centre (24, 16.5) radius 3.25 clockwise from (22.3032, 19.2719) to (24.5045, 19.7106)
  arc A2 centre (24, 16.5) radius 3.25 clockwise from (26.6357, 18.4015) to (27.2396, 16.2398)
  arc A3 centre (-24, 16.5) radius 4.85 clockwise from (-21.2417, 20.4893) to (-28.5609, 18.1494)
  circle C5 centre (-24, 16.5) radius 3.25
extrude "Extrude81" cut sketch "Sketch37" profile of C3 C4 A1 A2 L8 L12 L13 L14 L15 L16 along normal blind 45
extrude "Extrude50" add sketch "Sketch37" profile of C1 C2 C3 C4 against normal blind 2
extrude "Extrude51" cut sketch "Sketch37" profile of C2 C4 along normal blind 17
extrude "Extrude52" add sketch "Sketch37" profile of C2 along normal blind 5
extrude "Extrude54" cut sketch "Sketch36" profile of C3 C8 along normal blind 42
extrude "Extrude77" cut sketch "Sketch36" profile of C3 C13 along normal blind 20
extrude "Extrude78" add sketch "Sketch37" profile of C3 C4 A1 A2 L8 L12 L13 L14 L15 L16 against normal blind 17
extrude "Extrude79" add of existing geometry blind 0.8
component_insert "Component Insert6"
sketch "Sketch39" plane through (0, 0, 0) normal (0, -1, 0) x axis (1, 0, 0)
  line L1 (-32.8277, 28.8142) -> (-35.6561, 31.6426)
  line L2 (-31.4135, 30.2284) -> (-32.8277, 28.8142)
  line L3 (33.6, 2) -> (33.6, 24.9001)
  line L4 (35, 2) -> (33.6, 2)
  line L5 (35, 27.2231) -> (35, 2)
  line L6 (33.6, 20.8819) -> (38, 20.8819)
  line L7 (33.6, 2) -> (33.6, 20.8819)
  line L8 (38, 2) -> (33.6, 2)
  line L9 (38, 20.8819) -> (38, 2)
  line L10 (-34.2585, 33.0734) -> (-31.4135, 30.2284)
  line L11 (-35.6561, 31.6426) -> (-35.6561, 34.471)
  curve K1 (-22.7985, 33.6) -> (-34.2585, 33.0734)
  line L12 (-19, 33.6) -> (-22.7985, 33.6)
  curve K2 (-10.8513, 35.1624) -> (-19, 33.6)
  line L13 (45.0403, 62.0037) -> (35, 27.2231)
  curve K3 (-9.0663, 37.3967) -> (45.0403, 62.0037)
  line L14 (-22.8281, 35) -> (-19, 35)
  line L15 (-35.6561, 34.471) -> (-22.8281, 35)
  line L16 (33.6, 24.9001) -> (-10.8513, 35.1624)
  curve K4 (-19, 35) -> (-9.0663, 37.3967)
  line L17 (35, 21.8912) -> (28.841, 17.4507)
  point P7 (33.6, 2)
  point P12 (33.6, 2)
  point P11 (33.6, 20.8819)
  horizontal L6
  vertical L7
  horizontal L8
  vertical L9
  coincident P7 P12
  coincident P11 L17
extrude "Extrude56" cut sketch "Sketch39" profile of L3 L4 L5 L6 L7 L8 L9 against normal blind 19
sketch "Sketch40" plane through (0, 0, 0) normal (0, -1, 0) x axis (1, 0, 0)
  line L1 (35, 20.8819) -> (33.6, 20.8819)
  line L2 (-32.8277, 28.8142) -> (-35.6561, 31.6426)
  line L3 (-31.4135, 30.2284) -> (-32.8277, 28.8142)
  line L4 (-34.2585, 33.0734) -> (-31.4135, 30.2284)
  line L5 (-35.6561, 31.6426) -> (-35.6561, 34.471)
  line L6 (35, 27.2231) -> (35, 20.8819)
  line L7 (45.0403, 62.0037) -> (35, 27.2231)
  curve K1 (-9.0663, 37.3967) -> (45.0403, 62.0037)
  line L8 (-22.8281, 35) -> (-19, 35)
  line L9 (-35.6561, 34.471) -> (-22.8281, 35)
  curve K2 (-22.7985, 33.6) -> (-34.2585, 33.0734)
  line L10 (-19, 33.6) -> (-22.7985, 33.6)
  curve K3 (-10.8513, 35.1624) -> (-19, 33.6)
  line L11 (33.6, 20.8819) -> (33.6, 24.9001)
  curve K4 (-19, 35) -> (-9.0663, 37.3967)
  line L12 (33.6, 24.9001) -> (-10.8513, 35.1624)
sketch "Sketch53" plane through (0, 0, 12) normal (0, 0, -1) x axis (1, 0, 0)
  line L1 (27.734, -15.936) -> (27.2396, -16.2398)
  line L2 (28.5378, -14.7881) -> (27.734, -15.936)
  line L3 (22.3032, -19.2719) -> (20.8342, -20.1743)
  line L4 (22.3032, -19.2719) -> (19.9163, -20.7381)
  line L5 (27.734, -15.936) -> (28.5378, -14.7881)
  line L6 (27.7731, -12.3934) -> (27.7731, -12.1971)
  arc A1 centre (24, -16.5) radius 3.25 clockwise from (22.3032, -19.2719) to (27.2396, -16.2398)
  arc A2 centre (24, -16.5) radius 4.85 clockwise from (20.8342, -20.1743) to (28.5378, -14.7881)
  vertical L6
work_plane "WorkPlane6" RotateAngle 60
work_plane "WorkPlane7" AlongDistance 74
sketch "Sketch41" plane through (64.0859, 0, 37) normal (0.866, 0, 0.5) x axis (0, 1, 0)
  line L1 (0, -20) -> (0, 39.1526)
  line L2 (0, 39.1526) -> (0, 31.1767)
  circle C1 centre (0, 19) radius 3.5
  circle C2 centre (0, 19) radius 5.5
  point P2 (0, 19)
  point P4 (0, 39.1526)
  point P7 (0, 39.1526)
  coincident P2 L2
  concentric C1 C2
  coincident P4 P7
  parallel L1 L2
  dimension "d528" diameter C1 = 7
  dimension "d529" distance C1 C2 = 2
extrude "Extrude57" new body sketch "Sketch41" profile of L2 C1 C2 along a picked direction blind -75
combine "Combine9"
extrude "Extrude58" new body sketch "Sketch41" profile of L2 C1 C2 along a picked direction blind -83
combine "Combine10"
remove_body "RemoveBody31"
combine "Combine11" bodies "canopy (1)"
remove_body "RemoveBody33"
copy_paste_bodies "CopyPasteBodies4"
sketch "Sketch42" plane through (4.3331, 0, 41.6617) normal (0, -1, 0) x axis (1, 0, 0)
  line L1 (-57, -2) -> (27, -2)
  line L2 (-57, -40) -> (-57, -2)
  line L3 (27, -40) -> (-57, -40)
  line L4 (27, -2) -> (27, -40)
  horizontal L1
  vertical L2
  horizontal L3
  vertical L4
extrude "Extrude60" sketch "Sketch40" + "Sketch42" blind -13
combine "Combine13"
combine "Combine12"
remove_body "RemoveBody46"
work_plane "WorkPlane8" AlongDistance 50
sketch "Sketch43" plane through (0, 0, 50) normal (0, 0, 1) x axis (1, 0, 0)
  line L1 (-10, 8) -> (10, 8)
  line L2 (-10, 11) -> (-10, 8)
  line L3 (10, 11) -> (-10, 11)
  line L4 (-8, 11) -> (-8, 8)
  line L5 (16.9983, 9.3299) -> (16.9983, 6.3299)
  line L6 (18.9983, 6.3299) -> (18.9983, 9.3299)
  line L7 (-5.2116, 8) -> (-18.8897, 8)
  line L8 (-23.64, 0) -> (-29.64, 0)
  line L9 (-23.64, 7) -> (-23.64, 0)
  line L10 (-29.64, 0) -> (-29.64, 5)
  line L11 (-23.64, 7) -> (-29.64, 5)
  line L12 (16.9983, 6.3299) -> (18.9983, 6.3299)
  line L13 (16.9983, 9.3299) -> (18.9983, 9.3299)
  line L14 (10, 11) -> (10, 8)
  line L15 (55, 0) -> (-70, 0)
  circle C1 centre (0, 11) radius 2.5
  circle C2 centre (10.9983, 9.5) radius 2.5
  point P6 (-8, 8)
  point P7 (-8, 11)
  point P12 (-18.8897, 8)
  point P18 (0, 11)
  point P15 (-23.64, 0)
  point P2 (10, 8)
  point P3 (-10, 8)
  point P5 (10, 11)
  point P8 (18.9983, 6.3299)
  point P11 (18.9983, 9.3299)
  point P16 (-23.64, 7)
  point P19 (10.9983, 9.5)
  point P14 (-29.64, 0)
  point P17 (-29.64, 5)
  horizontal L1
  vertical L2
  horizontal L3
  coincident L1 P6
  coincident L3 P7
  perpendicular L3 L4
  vertical L6
  horizontal L7
  coincident L1 P12
  horizontal L8
  midpoint L3 P18
  vertical L10
  perpendicular L6 L12
  perpendicular L5 L13
  perpendicular L3 L14
  horizontal L15
  coincident P15 L15
  dimension "d545" distance P2 P3 = 20
  dimension "d546" distance P2 P5 = 3
  dimension "d548" distance L2 L4 = 2 (= "d547")
  dimension "d565" distance P8 P11 = 3
  dimension "d566" distance L5 L6 = 2
  dimension "d637" distance L9 L10 = 6
  dimension "d638" diameter C1 = 5
  dimension "d639" diameter C2 = 5
  dimension "d640" distance P15 P16 = 7
  dimension "d677" distance L5 P19 = 6
  dimension "d756" distance P14 P17 = 5
extrude "Extrude61" cut sketch "Sketch43" profile of L8 L9 L10 L11 against normal blind 33
sketch "Sketch51" plane through (0, 0, 0) normal (0, -1, 0) x axis (1, 0, 0)
  line L1 (-19, 33.6) -> (-22.7985, 33.6)
  curve K1 (-10.8513, 35.1624) -> (-19, 33.6)
  line L2 (45.0403, 62.0037) -> (41.5696, 49.981)
  curve K2 (-9.0663, 37.3967) -> (45.0403, 62.0037)
  line L3 (-22.8281, 35) -> (-19, 35)
  line L4 (-12.5299, 34.9665) -> (-23.64, 34.9665)
  line L5 (-12.5299, 27.0748) -> (-12.5299, 34.9665)
  line L6 (-23.64, 27.0748) -> (-12.5299, 27.0748)
  line L7 (-23.64, 34.9665) -> (-23.64, 27.0748)
  line L8 (8.2607, 30.7501) -> (-10.8513, 35.1624)
  curve K3 (-19, 35) -> (-9.0663, 37.3967)
  line L9 (-23.64, 33.5643) -> (-23.64, 34.9665)
  line L10 (41.5696, 49.981) -> (8.2607, 30.7501)
  curve K4 (-22.7985, 33.6) -> (-23.64, 33.5643)
  line L11 (-23.64, 34.9665) -> (-22.8281, 35)
  point P2 (-23.64, 34.9665)
  point P11 (-23.64, 34.9665)
  horizontal L4
  vertical L5
  horizontal L6
  vertical L7
  coincident P2 P11
extrude "Extrude67" new body sketch "Sketch51" profile of L1 K1 L5 L6 L7 against normal blind 24
copy_paste_bodies "CopyPasteBodies3"
combine "Combine22"
combine "Combine23"
remove_body "RemoveBody24"
combine "Combine24"
combine "Combine25"
work_plane "WorkPlane12" AlongDistance 10.5
sketch "Sketch46" plane through (0, 10.5, 0) normal (0, 1, 0) x axis (1, 0, 0)
  circle C1 centre (-31.43, -16.9) radius 1
  circle C2 centre (-31.43, -16.9) radius 4
  concentric C1 C2
  dimension "d604" diameter C1 = 2
  dimension "d605" diameter C2 = 8
extrude "Extrude63" new body sketch "Sketch46" along normal blind 13
combine "Combine14"
extrude "Extrude64" cut sketch "Sketch46" along normal blind 12
remove_body "RemoveBody45"
extrude "Extrude65" new body sketch "Sketch46" along normal blind 13
combine "Combine15"
remove_body "RemoveBody36"
work_plane "WorkPlane13" sketch "Sketch46" AlongDistance 12
sketch "Sketch47" plane through (0, 22.5, 0) normal (0, 1, 0) x axis (1, 0, 0)
  circle C1 centre (-31.43, -16.9) radius 1
  circle C2 centre (-31.43, -16.9) radius 3
  concentric C1 C2
  dimension "d613" diameter C2 = 6
extrude "Extrude66" cut sketch "Sketch47" against normal blind 9
combine "Combine16"
combine "Combine17"
sketch "Sketch49" plane through (0, 0, 19) normal (0, 0, 1) x axis (-1, 0, 0)
  line L1 (-21.9602, -12.9254) -> (-25.9602, -12.9254)
  line L2 (-21.9602, 0) -> (-21.9602, -12.9254)
  line L3 (-25.9602, 0) -> (-21.9602, 0)
  line L4 (-25.9602, -12.9254) -> (-25.9602, 0)
  line L5 (-20.8364, -17.2442) -> (-19.3192, -17.7698)
  line L6 (-28.4633, -14.6023) -> (-26.9461, -15.1278)
  circle C1 centre (-24, -16.5) radius 1.55
  arc A1 centre (-24, -16.5) radius 3.25 clockwise from (-26.9461, -15.1278) to (-20.8364, -17.2442)
  arc A2 centre (-24, -16.5) radius 4.85 clockwise from (-19.3192, -17.7698) to (-28.4633, -14.6023)
  horizontal L1
  vertical L2
  horizontal L3
  vertical L4
  dimension "d652" distance L2 L4 = 4
extrude "Extrude69" new body sketch "Sketch49" profile of L1 L2 L3 L4 along normal blind 11
extrude "Extrude70" add of existing geometry blind 7
copy_paste_bodies "CopyPasteBodies2"
combine "Combine18"
combine "Combine19"
remove_body "RemoveBody27"
combine "Combine20"
combine "Combine21"
sketch "snip-snip" plane through (0, 0, 0) normal (0, -1, 0) x axis (1, 0, 0)
  line L1 (-12.5299, 34.6056) -> (-12.5299, 27.0748)
  curve K1 (-10.8513, 35.1624) -> (-12.5299, 34.6056)
  line L2 (8.2607, 30.7501) -> (-10.8513, 35.1624)
  line L3 (41.5696, 49.981) -> (8.2607, 30.7501)
  line L4 (45.0403, 62.0037) -> (41.5696, 49.981)
  curve K2 (-9.0663, 37.3967) -> (45.0403, 62.0037)
  line L5 (-22.8281, 35) -> (-19, 35)
  line L6 (-29.64, 34.7191) -> (-29.64, 20.6204)
  line L7 (-23.64, 27.0748) -> (-23.64, 34.9665)
  line L8 (-12.5299, 27.0748) -> (-23.64, 27.0748)
  curve K3 (-19, 35) -> (-9.0663, 37.3967)
  line L9 (-18.8473, 11.5532) -> (-29.64, 20.6204)
  line L10 (-18.8473, -1.174) -> (-18.8473, 11.5532)
  line L11 (-29.64, 34.7191) -> (-29.64, 33.3021)
  line L12 (-23.64, 34.9665) -> (-22.8281, 35)
  circle C1 centre (-31.43, 16.9) radius 4
  point P11 (-29.64, 34.7191)
  point P19 (-29.64, 34.7191)
  vertical L6
  parallel L6 L10
  coincident P11 P19
  tangent L9 C1
split "Split2"
chamfer "Chamfer9" distance 12 Rotate Angle 35
fillet "Fillet106" radius 15
chamfer "Chamfer15" distance 4 distance 12
work_plane "WorkPlane15" RotateAngle -65
sketch "Sketch57" plane through (-25.2956, 11.7955, 0) normal (-0.9063, 0.4226, 0) x axis (0, 0, -1)
  line L1 (-2, -9.5925) -> (-13.5648, -9.5925)
split "Split3" bodies "canopy (1) (2)"
work_plane "WorkPlane16" RotateAngle -22
sketch "Sketch58" plane through (2.2959, 5.6824, 0) normal (0.3746, 0.9272, 0) x axis (0, 0, 1)
  line L1 (23.5746, -33.2801) -> (19.7139, -33.2801)
split "Split4" bodies "canopy-cam (2)", "canopy-cam (3)", "canopy (1) (1) (1)"
combine "Combine27" bodies "canopy (1) (2)"
combine "Combine28" bodies "canopy (1) (1) (1)", "canopy-cam (3)", "canopy-cam (2)"
fillet "Fillet129" radius 1.6
chamfer "Chamfer19" distance 1
chamfer "Chamfer21" distance 1.5
sketch "Sketch59" plane through (0, 0, 0) normal (0, -1, 0) x axis (1, 0, 0)
  line L1 (-48.6669, 21.4602) -> (-45.8385, 21.4602)
  line L2 (-42, 2) -> (-48.6669, 21.4602)
  line L3 (-41.4019, -7) -> (-42, 2)
  line L4 (-40.0019, -7) -> (-41.4019, -7)
  line L5 (-40.5206, 2) -> (-40.0019, -7)
  curve K1 (-46.313, 19.1063) -> (-40.5206, 2)
  line L6 (-44.4243, 17.2176) -> (-46.313, 19.1063)
  line L7 (-43.0101, 18.6318) -> (-44.4243, 17.2176)
  line L8 (-45.8385, 21.4602) -> (-43.0101, 18.6318)
  line L9 (-45.369, 16.2728) -> (-44.4243, 17.2176)
  line L10 (-34.2585, 33.0734) -> (-46.313, 19.1063)
  line L11 (-45.369, 16.2728) -> (-46.313, 19.1063)
  line L12 (-43.0101, 18.6318) -> (-44.4243, 17.2176)
  line L13 (-43.0101, 18.6318) -> (-31.4135, 30.2284)
  line L14 (-29.64, 33.3021) -> (-31.4135, 30.2284)
  line L15 (-29.64, 34.7191) -> (-29.64, 33.3021)
  line L16 (-34.2585, 33.0734) -> (-29.64, 34.7191)
  point P9 (-44.4243, 17.2176)
  point P11 (-44.4243, 17.2176)
  point P12 (-45.369, 16.2728)
  point P8 (-46.313, 19.1063)
  point P15 (-46.313, 19.1063)
  point P14 (-34.2585, 33.0734)
  point P16 (-34.2585, 33.0734)
  point P17 (-46.313, 19.1063)
  point P10 (-43.0101, 18.6318)
  point P18 (-43.0101, 18.6318)
  point P13 (-31.4135, 30.2284)
  point P19 (-31.4135, 30.2284)
  point P22 (-31.4135, 30.2284)
  point P20 (-29.64, 33.3021)
  point P23 (-29.64, 33.3021)
  point P21 (-29.64, 34.7191)
  point P24 (-29.64, 34.7191)
  point P25 (-34.2585, 33.0734)
  coincident P9 P11
  coincident K1 P12
  perpendicular L6 L9
  coincident P8 P15
  coincident P14 P16
  coincident P8 P17
  coincident P10 P18
  coincident P13 P19
  coincident P13 P22
  coincident P20 P23
  coincident P21 P24
  coincident P14 P25
extrude "Extrude88" new body sketch "Sketch59" profile of L6 L7 L8 L9 L10 L11 L12 L13 L14 L15 L16 against normal blind 19
combine "Combine31"
remove_body "RemoveBody49"
remove_body "RemoveBody50"
combine "Combine32"
extrude "Extrude93" add of existing geometry blind 0.2
fillet "Fillet117" radius 12
fillet "Fillet118" radius 15
fillet "Fillet127" radius 1.5
sketch "led slot" plane through (0, 0, 0) normal (0, -1, 0) x axis (1, 0, 0)
  curve K1 (14.6205, 53.0546) -> (43.6386, 62.4985)
  curve K2 (-9.0663, 37.3967) -> (14.6205, 53.0546)
  line L1 (-22.8281, 35) -> (-19, 35)
  line L2 (-12.5299, 34.6056) -> (-12.5299, 27.0748)
  curve K3 (-10.8513, 35.1624) -> (-12.5299, 34.6056)
  line L3 (8.2607, 30.7501) -> (-10.8513, 35.1624)
  line L4 (41.5696, 49.981) -> (8.2607, 30.7501)
  line L5 (44.1511, 58.9235) -> (41.5696, 49.981)
  line L6 (36.7693, 58.4653) -> (-5.666, 33.9653)
  line L7 (39.7193, 53.3558) -> (2.7633, 32.0193)
  line L8 (36.7693, 58.4653) -> (39.7193, 53.3558)
  curve K4 (-23.64, 34.9665) -> (-12.5299, 27.0748)
  curve K5 (-19, 35) -> (-9.0663, 37.3967)
  line L9 (-23.64, 34.9665) -> (-22.8281, 35)
  curve K6 (44.1511, 58.9235) -> (43.6386, 62.4985)
  point P12 (-5.666, 33.9653)
  point P14 (2.7633, 32.0193)
  point P13 (36.7693, 58.4653)
  coincident L3 P12
  parallel L4 L6
  coincident L3 P14
  parallel L6 L7
  perpendicular L7 L8
  dimension "d945" distance L6 L7 = 5.9
  dimension "d951" distance P12 P13 = 49
extrude "Extrude87" cut sketch "led slot" profile of L3 L6 L7 L8 against normal blind 1.4
fillet "Fillet163" radius 3
fillet "Fillet148" radius 1.4
fillet "Fillet149" radius 2
fillet "Fillet151" radius 3
fillet "Fillet162" radius 22
fillet "Fillet155" radius 8
fillet "Fillet160" radius 9
fillet "Fillet161" radius 0.5
fillet "Fillet164" radius 2
fillet "Fillet165" radius 0.3
split "Split5" bodies "canopy-cam (1) (1)"
work_plane "WorkPlane17" RotateAngle -50
split "Split6" bodies "canopy-cam (1) (1) (1)"
combine "Combine33" bodies "canopy-cam (1) (1) (1)"
combine "Combine34" bodies "canopy-cam (1) (1)"
fillet "Fillet168" radius 2
fillet "Fillet170" radius 1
